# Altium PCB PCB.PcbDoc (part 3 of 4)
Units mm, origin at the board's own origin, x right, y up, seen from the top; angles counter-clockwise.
Board outline 114 x 86.5 mm, 4 copper layers (TOP, GND, SIG, BOTTOM), stack 1.586 mm thick; 98 components, 195 nets, 719 pads, 522 vias.
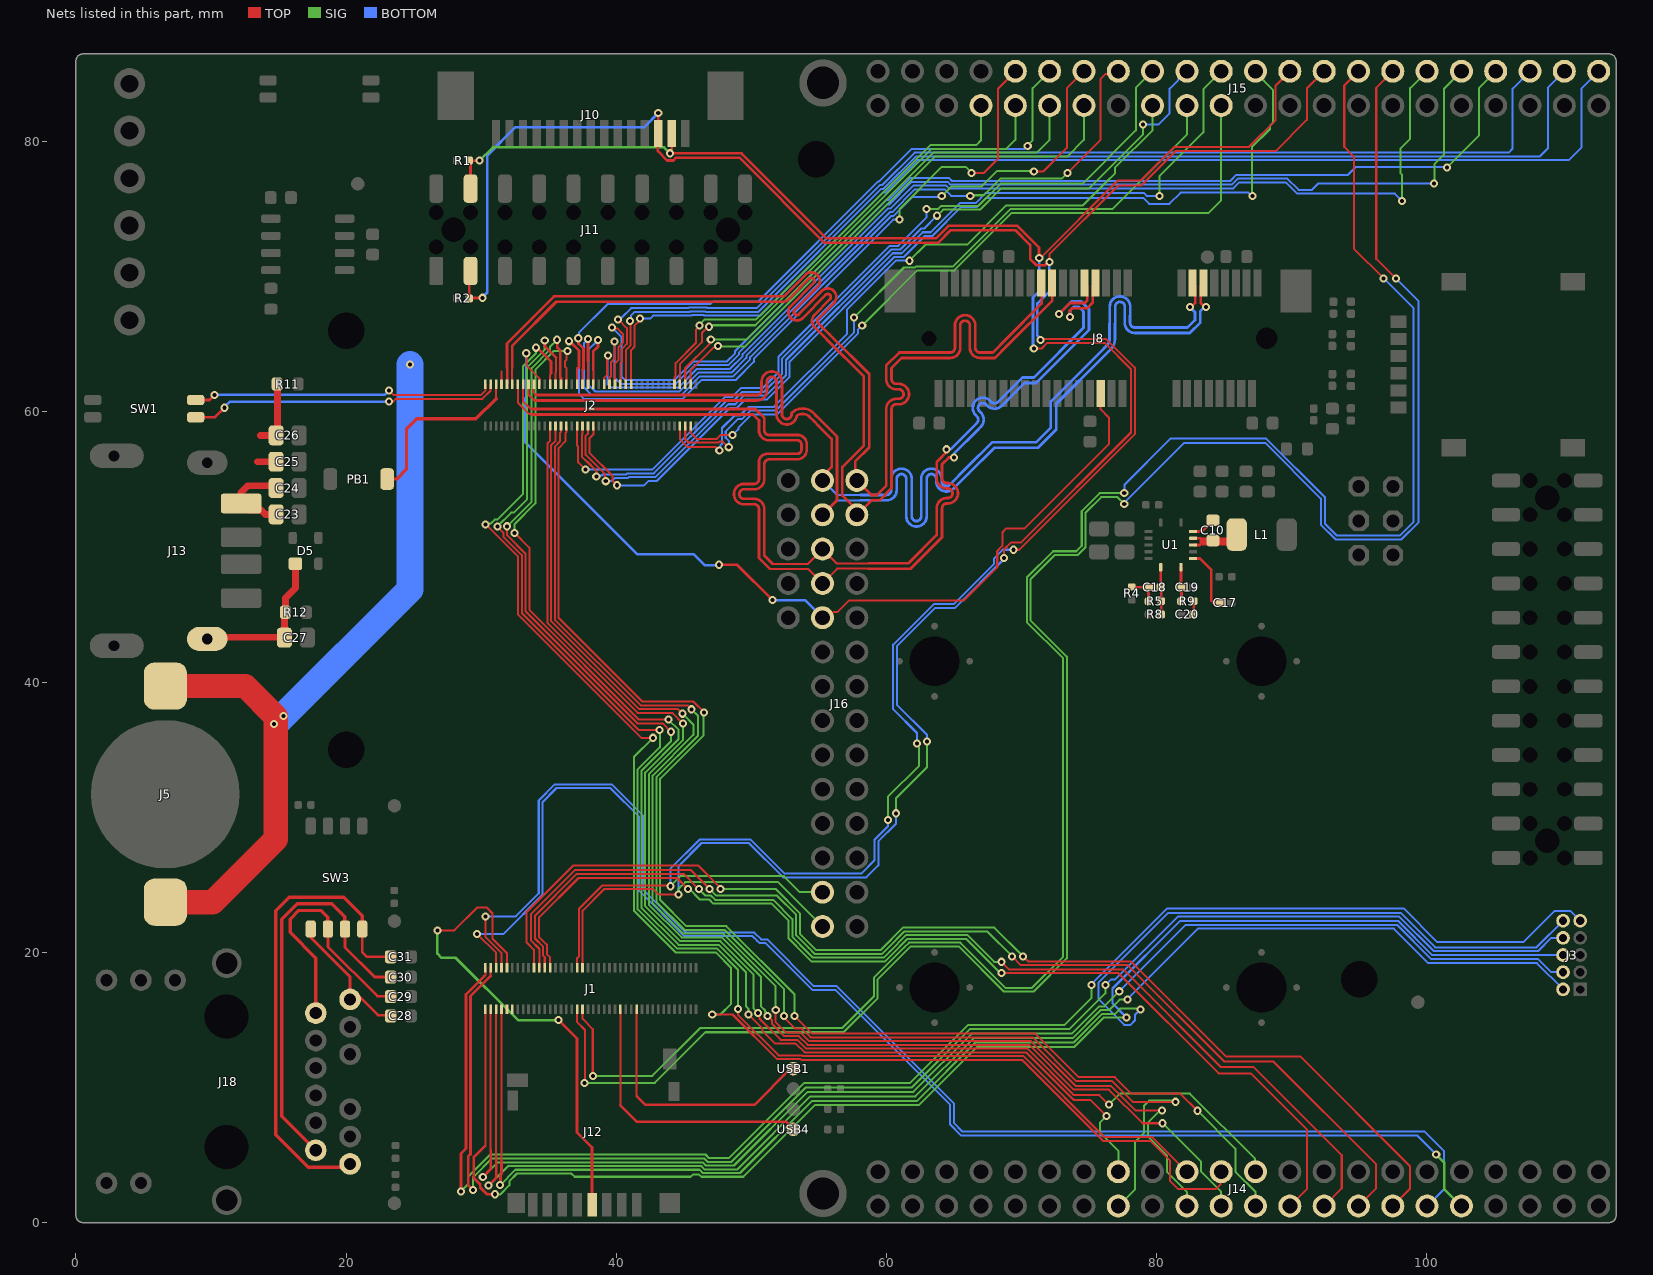
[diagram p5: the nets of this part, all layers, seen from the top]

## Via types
v1: diameter 0.6, hole 0.3, TOP to BOTTOM, tented both sides, 522 vias

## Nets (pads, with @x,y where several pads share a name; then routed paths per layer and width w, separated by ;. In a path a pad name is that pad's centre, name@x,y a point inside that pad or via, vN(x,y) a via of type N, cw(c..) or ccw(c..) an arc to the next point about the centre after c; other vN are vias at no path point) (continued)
I2C0.SCL_1: J1.46 J10.13 J11.3 J15.28 J16.25 R2.1 | length 197
  TOP w0.15: J1.46@37.1,18.86 37.1,19.567 37.222,19.689 37.222,23.207 38.974,24.959 43.932,24.959 v1(43.998,24.892) ; v1(69.39,49.801) 69.813,49.801 78.375,58.363 78.375,63.28 76.263,65.392 71.458,65.392 v1(71.388,65.322) ; v1(72.05,71.096) 72.05,71.669 77.145,76.764 78.856,76.764 81.393,79.301 88.803,79.301 91.12,81.617 91.12,83.946 J15.28@92.394,85.22
  TOP w0.2: J11.3@29.21,70.435 29.117,70.342 R2.1@29.117,68.411 29.137,68.431 30.067,68.431 v1(30.088,68.452) ; v1(43.103,82.118) 43.103,80.603 43.068,80.568 43.068,79.316 43.763,78.621 44.218,78.621 44.418,78.821 49.124,78.821 55.421,72.523 63.795,72.523 64.721,73.449 69.545,73.449 70.633,72.361 70.633,71.313 71.087,70.859 71.733,70.859 71.969,71.096 v1(72.05,71.096)
  SIG w0.15: v1(43.998,24.892) 44.741,25.635 52.397,25.635 53.582,24.449 J16.25@55.264,24.449 ; v1(60.098,29.792) 60.098,31.503 62.418,33.823 62.418,35.173 62.255,35.335 v1(62.255,35.457)
  BOTTOM w0.15: v1(43.998,24.892) 43.998,26.177 46.191,28.369 49.921,28.369 52.465,25.826 56.641,25.826 58.128,25.826 59.098,26.796 59.098,28.315 60.098,29.315 v1(60.098,29.792) ; v1(62.255,35.457) 62.255,36.233 60.494,37.995 60.494,42.768 63.498,45.772 64.965,45.772 67.966,48.772 67.966,49.17 68.597,49.801 v1(69.39,49.801)
  BOTTOM w0.2: v1(30.088,68.452) 30.088,68.489 30.442,68.843 30.442,78.99 32.538,81.086 42.071,81.086 v1(43.103,82.118) ; v1(71.388,65.322) 71.388,65.414 71.162,65.64 71.162,68.037 72.05,68.925 v1(72.05,71.096)
I2C0.SDA_1: J1.44 J10.14 J11.4 J15.26 J16.27 R1.1 | length 183.1
  TOP w0.15: J1.44@37.5,18.86 37.499,23.093 39.088,24.682 42.718,24.682 43.108,24.292 v1(44.598,24.292) ; v1(68.698,49.192) 68.698,49.819 69.209,50.33 69.95,50.33 78.098,58.478 78.098,63.165 76.155,65.109 71.884,65.109 71.475,64.7 v1(70.9,64.7) ; v1(71.305,71.386) 71.375,71.386 77.122,77.133 78.833,77.133 81.312,79.612 86.807,79.612 88.802,81.607 88.802,84.168 J15.26@89.854,85.22
  TOP w0.2: R1.1@29.1,78.6 29.112,78.612 R1.1@29.117,78.612 R1.1@29.128,78.601 ; J11.4@29.21,76.535 29.21,78.519 R1.1@29.128,78.601 ; v1(29.875,78.601) R1.1@29.128,78.601 ; J10.14@44.1,80.6 44.1,79.266 v1(43.982,79.148) 49.259,79.148 55.557,72.85 63.66,72.85 64.585,73.776 69.68,73.776 71.28,72.177 71.28,71.411 v1(71.305,71.386)
  SIG w0.15: v1(44.598,24.292) 44.598,24.702 45.09,25.194 51.979,25.194 J16.27@55.264,21.909 ; v1(60.698,30.292) 60.698,31.392 62.986,33.68 62.986,35.58 v1(62.998,35.592)
  SIG w0.2: v1(29.875,78.601) 30.864,79.59 43.539,79.59 v1(43.982,79.148)
  BOTTOM w0.15: v1(44.598,24.292) 44.598,26.385 46.305,28.092 49.807,28.092 52.35,25.549 58.512,25.549 59.401,26.438 59.401,28.226 60.698,29.524 v1(60.698,30.292) ; v1(62.998,35.592) 62.998,36.092 60.771,38.32 60.771,42.653 63.613,45.495 65.08,45.495 68.698,49.113 v1(68.698,49.192)
  BOTTOM w0.2: v1(70.9,64.7) 70.835,64.765 70.835,68.461 71.305,68.931 v1(71.305,71.386)
I2S.CK_1: J1.56 J14.25 | length 78.2
  TOP w0.15: J1.56@35.1,18.86 35.1,19.628 34.856,19.872 34.856,20.571 34.271,21.155 34.271,22.571 37.2,25.5 44.491,25.5 v1(45.298,24.692) ; v1(68.516,18.47) 77.158,18.47 84.583,11.045 86.955,11.045 91.13,6.87 91.13,2.496 J14.25@89.854,1.22
  SIG w0.15: v1(45.298,24.692) 45.388,24.692 46.167,23.913 46.877,23.913 47.188,23.602 51.498,23.602 52.755,22.345 52.755,21.756 52.755,21.024 53.998,19.781 54.441,19.338 59.9,19.338 60.342,19.781 61.553,20.991 65.883,20.991 68.404,18.47 v1(68.516,18.47)
I2S.SDI_1: J1.60 J14.29 | length 83.1
  TOP w0.15: J1.60@34.3,18.86 34.3,20.247 34.277,20.27 34.277,20.285 33.674,20.887 33.674,22.828 36.95,26.104 45.487,26.104 v1(46.898,24.692) ; v1(69.3,19.7) 69.951,19.049 77.857,19.049 84.986,11.92 88.638,11.92 96.219,4.339 96.219,2.505 J14.29@94.934,1.22
  SIG w0.15: v1(46.898,24.692) 47.4,24.19 51.894,24.19 53.309,22.775 53.309,21.985 53.309,21.254 54.227,20.335 54.67,19.892 59.67,19.892 60.113,20.335 61.323,21.545 67.455,21.545 v1(69.3,19.7)
I2S.SDO_1: J1.62 J14.31 | length 86.2
  TOP w0.15: J1.62@33.9,18.86 33.9,20.199 33.347,20.752 33.347,22.964 36.814,26.431 46.059,26.431 47.698,24.792 v1(47.698,24.692) ; v1(70.1,19.7) 70.474,19.326 78.088,19.326 85.119,12.296 90.622,12.296 98.75,4.168 98.75,2.496 J14.31@97.474,1.22
  SIG w0.15: v1(47.698,24.692) 51.783,24.692 53.586,22.89 53.586,21.368 54.785,20.169 59.555,20.169 61.208,21.822 67.978,21.822 v1(70.1,19.7)
I2S.WS_1: J1.58 J14.27 | length 80.2
  TOP w0.15: J1.58@34.7,18.86 34.7,19.636 34.579,19.758 34.579,20.421 33.976,21.023 33.976,22.703 37.075,25.802 44.988,25.802 v1(46.108,24.682) ; v1(68.5,19.3) 69.053,18.747 77.517,18.747 84.756,11.508 87.178,11.508 93.696,4.99 93.696,2.522 J14.27@92.394,1.22
  SIG w0.15: v1(46.108,24.682) 46.6,24.19 47.009,24.19 47.32,23.879 51.613,23.879 53.032,22.46 53.032,21.871 53.032,21.139 54.113,20.058 54.556,19.615 59.785,19.615 60.228,20.058 61.438,21.268 65.998,21.268 67.966,19.3 v1(68.5,19.3)
JTAG.R\E\S\E\T\_1: J1.73 J3.10 | length 110.3
  TOP w0.15: 31.5,4.538 J1.73@31.5,15.78
  TOP w0.2: v1(31.395,2.772) 31.427,2.805 31.427,3.517 31.5,3.59 31.5,4.538
  SIG w0.15: v1(31.395,2.772) 32.529,3.907 46.161,3.907 46.402,3.665 49.156,3.665 54.503,9.013 62.263,9.013 66.577,13.327 73.851,13.327 75.976,15.452 76.922,15.452 77.301,15.832 78.746,15.832 v1(78.804,15.774)
  BOTTOM w0.15: v1(78.804,15.774) 78.395,15.365 78.395,14.959 78.073,14.636 77.595,14.636 75.695,16.536 75.695,17.783 80.839,22.927 98.065,22.927 100.617,20.374 108.113,20.374 J3.10@110.079,22.34
JTAG.TCK/SCK_1: J1.77 J3.4 | length 102
  TOP w0.15: 30.7,5.349 J1.77@30.7,15.78
  TOP w0.2: v1(30.114,3.358) 30.7,3.944 30.7,5.349
  SIG w0.15: v1(30.114,3.358) 31.217,4.461 46.39,4.461 46.632,4.219 48.707,4.219 54.155,9.667 61.992,9.667 66.306,13.981 73.722,13.981 75.747,16.006 76.117,16.006 v1(77.227,17.116)
  BOTTOM w0.15: v1(77.227,17.116) 82.142,22.031 97.785,22.031 100.293,19.523 108.208,19.523 109.201,18.53 J3.4@110.079,18.53
JTAG.TDI_1: J1.78 J3.8 | length 108.9
  TOP w0.15: 30.7,18.256 J1.78@30.7,18.86
  TOP w0.2: v1(29.4,2.4) 29.036,2.764 29.036,4.892 29.198,5.055 29.198,16.754 30.7,18.256
  SIG w0.15: v1(29.4,2.4) 29.4,3.353 30.784,4.738 46.505,4.738 46.747,4.496 48.522,4.496 54.019,9.994 61.857,9.994 66.17,14.308 73.536,14.308 76.197,16.969 v1(76.197,17.575)
  BOTTOM w0.15: v1(76.197,17.575) 76.601,17.979 76.895,17.979 81.566,22.65 97.95,22.65 100.503,20.097 108.228,20.097 109.201,21.07 J3.8@110.079,21.07
JTAG.TDO/SWO_1: J1.79 J3.6 | length 106.8
  TOP w0.15: 30.3,5.694 J1.79@30.3,15.78
  TOP w0.2: 30.3,5.694 29.45,4.844 29.45,3.276 29.927,2.799 29.927,2.594 30.429,2.092 v1(31.019,2.092)
  SIG w0.15: v1(31.019,2.092) 31.424,2.092 32.087,2.754 32.087,3.071 32.646,3.63 36.671,3.63 36.913,3.388 45.504,3.388 45.688,3.572 46.104,3.572 46.288,3.388 49.402,3.388 54.7,8.686 62.398,8.686 66.712,13 73.916,13 76.091,15.175 v1(77.766,15.175)
  BOTTOM w0.15: v1(77.766,15.175) 76.725,16.216 76.725,17.324 81.709,22.308 97.9,22.308 100.408,19.8 J3.6@110.079,19.8
JTAG.TMS/SWD_1: J1.75 J3.2 | length 102.8
  TOP w0.15: 31.1,4.883 J1.75@31.1,15.78
  TOP w0.2: v1(30.534,2.732) 31.1,3.298 31.1,4.883
  SIG w0.15: v1(30.534,2.732) 31.986,4.184 46.276,4.184 46.517,3.942 48.97,3.942 54.368,9.34 62.128,9.34 66.441,13.654 73.786,13.654 75.861,15.729 76.489,15.729 77.26,16.5 v1(77.85,16.5)
  BOTTOM w0.15: v1(77.85,16.5) 77.85,16.566 83.039,21.754 97.557,21.754 100.111,19.2 108.139,19.2 J3.2@110.079,17.26
JTAG.TRST_1: J1.80 J3.9 | length 112.3
  TOP w0.15: 30.206,18.224 30.3,18.319 J1.80@30.3,18.86
  TOP w0.2: v1(28.5,2.3) 28.5,5.107 28.871,5.478 28.871,16.89 30.206,18.224
  SIG w0.15: v1(28.5,2.3) 29.02,2.82 29.02,3.389 30.666,5.035 46.599,5.035 46.861,4.773 48.336,4.773 53.884,10.321 61.721,10.321 66.035,14.635 73.18,14.635 75.161,16.616 v1(75.161,17.59)
  BOTTOM w0.15: v1(75.161,17.59) 75.161,17.64 80.771,23.25 98.282,23.25 100.773,20.758 107.138,20.758 109.43,23.05 110.639,23.05 J3.9@111.349,22.34
LICELL_1: J2.7 J5.1 J5.2 | length 59.7
  TOP w0.15: J2.7@31.5,62.04 31.5,62.978
  TOP w1.8: J5.1@6.618,23.712 10.134,23.712 14.794,28.372 14.794,37.445 12.527,39.712 J5.2@6.618,39.712
  BOTTOM w2: 14.927,37.064 v1(15.369,37.506) 24.723,46.86 v1(24.723,63.509)
  other v1: 14.669,36.906
mPCIe_CK_N: J2.19 J8.11 J16.3 | length 86.5
  TOP w0.15: J2.19@33.9,62.04 33.884,62.024 33.884,61.435 34.049,61.269
  TOP w0.2: 34.049,61.269 34.067,61.252 50.096,61.252 50.396,61.252 ccw(c50.396,61.606) 50.75,61.606 50.75,62.246 cw(c51.504,62.246) 52.258,62.246 52.258,59.825 ccw(c52.612,59.825) 52.966,59.825 cw(c53.166,59.825) 53.036,59.977 cw(c53.784,59.109) 54.593,59.92 54.798,59.716 55,59.514 56.341,58.172 56.341,53.466 55.612,52.737 55.264,52.737 J16.3@55.264,52.389 ; J8.11@83.456,69.55 83.26,69.354 83.26,68.053 83.552,67.761 v1(83.651,67.761)
  BOTTOM w0.15: J16.3@55.264,52.389 56.334,53.459 58.08,53.459
  BOTTOM w0.2: 58.08,53.459 59.7,53.459 60,53.459 ccw(c60,54.213) 60.754,54.213 60.754,55.052 cw(c61.108,55.052) 61.462,55.052 61.462,52.277 ccw(c62.216,52.277) 62.97,52.277 62.97,55.052 cw(c63.324,55.052) 63.678,55.052 63.678,54.866 ccw(c64.432,54.866) 64.965,54.333 66.076,55.444 67.982,57.349 71.223,57.349 72.564,58.691 72.564,60.607 76.121,64.164 76.574,64.617 ccw(c75.763,65.426) 76.909,65.416 76.929,67.803 cw(c77.283,67.799) 77.286,68.153 ccw(c77.288,68.353) 77.287,68.153 cw(c77.283,67.799) 77.637,67.795 77.627,66.611 ; 77.627,66.61 ccw(c78.381,66.603) 78.381,65.849 80.064,65.849 82.446,65.849 83.23,66.633 83.23,67.459 v1@83.391,67.621
mPCIe_CK_P: J2.17 J8.13 J16.1 | length 83.1
  TOP w0.15: J2.17@33.5,62.04 33.5,61.288 33.937,60.852
  TOP w0.2: 33.937,60.852 50.096,60.852 50.396,60.852 ccw(c50.396,61.606) 51.15,61.606 51.15,62.246 cw(c51.504,62.246) 51.858,62.246 51.858,59.825 ccw(c52.612,59.825) 53.359,59.722 cw(c53.784,59.109) 54.31,59.637 54.617,59.331 54.976,58.971 55.941,58.007 55.941,55.914 55.264,55.237 J16.1@55.264,54.929 ; v1(82.451,67.761) 82.55,67.761 82.842,68.053 82.842,69.364 J8.13@82.656,69.55
  BOTTOM w0.15: J16.1@55.264,54.929 56.334,53.859 58.08,53.859
  BOTTOM w0.2: 58.08,53.859 59.7,53.859 60,53.859 ccw(c60,54.213) 60.354,54.213 60.354,55.052 cw(c61.108,55.052) 61.862,55.052 61.862,52.277 ccw(c62.216,52.277) 62.57,52.277 62.57,55.052 cw(c63.324,55.052) 64.078,55.052 64.078,54.866 ccw(c64.432,54.866) 64.682,54.616 65.973,55.906 67.816,57.749 71.057,57.749 72.164,58.856 72.164,60.773 76.126,64.734 76.291,64.899 ccw(c75.763,65.426) 76.509,65.42 76.529,67.805 cw(c77.283,67.799) 77.29,68.553 cw(c77.283,67.799) 78.033,67.882 78.037,67.877 78.037,67.805 cw(c77.283,67.799) 78.037,67.794 78.027,66.605 ccw(c78.381,66.603) 78.381,66.249 80.067,66.249 82.28,66.249 82.83,66.799 82.83,67.382 v1(82.451,67.761)
mPCIe_RST: J2.21 J8.22 J16.9 | length 68.6
  TOP w0.15: v1(33.333,64.347) 33.333,63.457 34.3,62.49 J2.21@34.3,62.04 ; J16.9@55.264,44.769 55.67,44.769 56.1,45.2 56.376,45.2 57.226,46.049 65.736,46.049 68.196,48.51 68.196,49.709 68.576,50.089 68.576,51.08 68.877,51.381 70.218,51.381 76.462,57.625 76.462,59.588 75.856,60.194 J8.22@75.856,61.35
  TOP w0.2: v1(47.598,48.692) 48.947,48.692 v1(51.567,46.071)
  BOTTOM w0.2: v1(33.333,64.347) 33.333,61.063 33.23,60.96 33.23,57.783 41.555,49.459 45.739,49.459 46.548,48.649 47.556,48.649 v1(47.598,48.692) ; v1(51.567,46.071) 53.962,46.071 J16.9@55.264,44.769
mPCIe_RX_N: J2.15 J8.23 J16.5 | length 83.1
  TOP w0.15: J2.15@33.1,62.04 33.075,62.015 33.075,61.715 33.075,60.806 33.646,60.236 33.681,60.236 ; 51.574,48.762 51.599,48.737 54.152,48.737 J16.5@55.264,49.849 56.328,48.786 58.7,48.786
  TOP w0.2: 33.681,60.236 33.699,60.218 50.282,60.218 50.955,59.545 50.955,58.645 ccw(c51.3,58.645) 51.3,58.3 53.4,58.3 cw(c53.4,57.6) 54.1,57.6 54.1,57.218 cw(c53.382,57.218) 53.382,56.5 51.34,56.5 ccw(c51.34,56.115) 50.955,56.115 50.955,56.105 50.955,55.028 cw(c50.201,55.028) 50.201,54.274 49.454,54.274 ccw(c49.454,53.92) 49.454,53.566 50.201,53.566 cw(c50.201,52.812) 50.955,52.812 50.955,52.512 50.955,49.357 51.549,48.762 51.574,48.762 ; 58.7,48.8 61.619,48.8 63.71,50.891 63.71,51.964 63.71,52.873 cw(c64.464,52.873) 64.464,53.627 64.532,53.627 ccw(c64.532,53.981) 64.532,54.335 64.464,54.335 cw(c64.464,55.089) 63.71,55.089 63.71,55.389 63.71,56.295 63.827,56.412 64.45,57.035 v1(64.45,57.237) ; v1(73.585,67.022) 73.562,67.045 73.562,67.494 73.736,67.667 74.839,67.667 75.256,68.084 75.256,69.35 J8.23@75.456,69.55
  BOTTOM w0.2: v1(64.45,57.237) 64.747,57.237 66.475,58.966 66.687,59.178 ccw(c66.437,59.428) 66.687,59.679 66.596,59.77 cw(c67.129,60.303) 66.596,60.836 cw(c67.129,60.303) 67.662,60.836 67.738,60.761 67.754,60.744 ccw(c68.004,60.995) 68.254,60.745 69.277,61.768 70.06,62.55 70.901,62.55 74.585,66.234 74.585,67.436 74.248,67.773 73.853,67.773 73.575,67.495 73.575,67.032 v1(73.585,67.022)
mPCIe_RX_P: J2.13 J8.25 J16.7 | length 85.6
  TOP w0.15: J2.13@32.7,62.04 32.725,62.015 32.725,60.661 33.543,59.843 33.75,59.843 33.775,59.818 ; 51.361,48.385 51.498,48.385 51.5,48.387 54.186,48.387 J16.7@55.264,47.309 56.351,48.397 58.666,48.397 58.667,48.395
  TOP w0.2: 33.775,59.818 50.116,59.818 50.555,59.379 50.555,58.645 ccw(c51.3,58.645) 51.3,57.9 53.4,57.9 cw(c53.4,57.6) 53.7,57.6 53.7,57.218 cw(c53.382,57.218) 53.382,56.9 51.174,56.9 ccw(c51.174,56.281) 50.555,56.281 50.555,56.105 50.555,55.028 cw(c50.201,55.028) 50.201,54.674 49.454,54.674 ccw(c49.454,53.92) 49.454,53.166 50.201,53.166 cw(c50.201,52.812) 50.555,52.812 50.555,52.512 50.555,49.191 51.361,48.385 ; 58.667,48.395 61.78,48.395 64.11,50.725 64.11,51.964 64.11,52.873 cw(c64.464,52.873) 64.464,53.227 64.532,53.227 ccw(c64.532,53.981) 64.532,54.735 64.464,54.735 cw(c64.464,55.089) 64.11,55.089 64.11,55.389 64.11,56.13 64.611,56.631 v1(65,56.631) ; v1@72.764,67.261 73.57,68.067 74.673,68.067 74.856,68.25 74.856,69.35 J8.25@74.656,69.55
  BOTTOM w0.2: v1(65,56.631) 65.003,56.631 65.003,56.928 66.758,58.683 66.97,58.895 ccw(c66.437,59.428) 67.029,59.896 67.029,59.903 66.879,60.053 cw(c67.129,60.303) 66.879,60.553 cw(c67.129,60.303) 67.38,60.553 67.47,60.463 ccw(c68.004,60.995) 68.537,60.462 69.56,61.485 70.225,62.15 71.066,62.15 74.985,66.069 74.985,67.602 74.414,68.173 73.688,68.173 v1(72.764,67.249)
mPCIe_TX_N: J2.11 J8.31 J16.4 | length 88.1
  TOP w0.15: J2.11@32.3,62.04 32.275,62.065 32.275,62.365 32.275,63.249 32.3,63.274
  TOP w0.2: 32.3,63.274 32.3,64.905 35.554,68.159 46.606,68.159 ; 46.606,68.158 51.556,68.158 52.328,68.158 ccw(c52.328,68.785) 52.775,68.346 54.271,69.867 cw(c54.433,69.709) 54.593,69.87 cw(c54.433,69.709) 54.596,69.55 52.858,67.783 52.858,67.774 ccw(c53.362,67.402) 52.863,67.023 52.863,67.014 52.916,66.961 ccw(c53.362,67.402) 52.922,66.956 52.98,66.897 52.99,66.897 ccw(c53.362,67.402) 53.809,66.962 ccw(c53.667,67.102) 53.81,66.963 55.489,68.67 ; 54.66,66.292 cw(c55.103,66.736) 54.656,67.176 55.813,68.353 ccw(c55.651,68.511) 55.811,68.673 cw(c55.95,68.816) 55.81,68.674 ccw(c55.651,68.511) 55.489,68.67 ; 54.661,66.292 55.494,65.459 55.649,65.304 58.319,62.633 58.319,57.531 56.727,55.938 56.727,53.814 57.804,52.737 J16.4@57.804,52.389 58.874,53.459 59.465,53.459 60.372,54.366 60.372,58.996 60.372,60.216 cw(c60.726,60.216) 60.726,60.57 60.906,60.57 ccw(c60.906,61.324) 60.906,62.078 60.726,62.078 cw(c60.726,62.432) 60.372,62.432 60.372,62.732 60.372,63.257 61.114,64 64.408,64 64.708,64 ccw(c64.708,64.754) 65.462,64.754 65.462,66.406 cw(c65.816,66.406) 66.17,66.406 66.17,64.754 ccw(c66.924,64.754) 66.924,64 68.032,64 68.9,64.868 72.273,68.24 J8.31@72.273,69.667
mPCIe_TX_P: J2.9 J8.33 J16.2 | length 85.4
  TOP w0.15: J2.9@31.9,62.04 31.925,62.065 31.925,62.365 31.925,63.249 31.9,63.274
  TOP w0.2: 31.9,63.274 31.9,65.071 35.388,68.559 46.772,68.559 51.684,68.558 52.328,68.558 ccw(c52.328,68.785) 52.489,68.626 53.987,70.149 ; 53.987,70.149 cw(c54.433,69.709) 53.993,70.155 54.046,70.208 54.054,70.208 cw(c54.433,69.709) 54.873,70.156 ; 54.873,70.156 cw(c54.433,69.709) 54.88,70.149 54.932,70.096 54.932,70.088 cw(c54.433,69.709) 54.88,69.269 ; 54.88,69.268 53.201,67.561 ccw(c53.362,67.402) 53.203,67.24 ccw(c53.362,67.402) 53.523,67.242 55.204,68.951 ; 55.205,68.952 cw(c55.651,68.511) 55.211,68.957 55.264,69.011 55.272,69.011 cw(c55.651,68.511) 56.091,68.958 cw(c55.651,68.511) 56.098,68.072 ; 56.098,68.071 54.941,66.895 ccw(c55.103,66.736) 54.942,66.576 55.777,65.742 55.929,65.589 58.719,62.799 58.719,57.365 57.679,56.324 57.679,55.055 J16.2@57.804,54.929 58.874,53.859 59.299,53.859 59.972,54.532 59.972,58.996 59.972,60.216 cw(c60.726,60.216) 60.726,60.97 60.906,60.97 ccw(c60.906,61.324) 60.906,61.678 60.726,61.678 cw(c60.726,62.432) 59.972,62.432 59.972,62.732 59.972,63.423 60.949,64.4 64.408,64.4 64.708,64.4 ccw(c64.708,64.754) 65.062,64.754 65.062,66.406 cw(c65.816,66.406) 66.57,66.406 66.57,64.754 ccw(c66.924,64.754) 66.924,64.4 67.867,64.4 68.9,65.433 71.481,68.014 J8.33@71.481,69.626
NetC10_1: C10.1 U1.13 | length 1.8
  TOP w0.2: U1.13@82.699,51.159 83.338,51.159 C10.1@84.163,51.984
NetC10_2: C10.2 L1.1 U1.11 U1.12 | length 4.4
  TOP w0.2: U1.11@82.699,50.159 83.194,50.159 83.459,50.424 83.224,50.659 U1.12@82.699,50.659
  TOP w0.6: 83.459,50.424 85.423,50.424 L1.1@85.925,50.926
NetC17_1: C17.1 U1.9 | length 4.6
  TOP w0.2: U1.9@82.699,49.159 83.197,49.159 84.032,48.324 84.032,46.054 84.19,45.895 C17.1@84.655,45.895
NetC18_1: C18.1 R5.1 R8.2 U1.7 | length 3.5
  TOP w0.2: U1.7@80.299,48.509 C18.1@80.299,47.025 80.339,46.985 R5.1@80.339,45.994 R8.2@80.339,45.013
NetC18_2: C18.2 R4.1 R5.2 | length 2.3
  TOP w0.2: R4.1@78.155,47.046 78.176,47.025 C18.2@79.429,47.025 79.389,46.985 R5.2@79.389,45.994
NetC19_2: C19.2 R9.2 U1.8 | length 2.5
  TOP w0.2: R9.2@81.794,45.994 81.834,46.034 C19.2@81.834,47.025 81.799,47.06 U1.8@81.799,48.509
NetC20_2: C20.2 R9.1 | length 1
  TOP w0.2: C20.2@82.704,45.013 82.744,45.053 R9.1@82.744,45.994
NetC23_2: C23.2 C24.2 C25.2 C26.2 J13.1 R11.2 | length 12.8
  TOP w0.5: 13.414,56.318 C25.2@14.814,56.318 ; 13.636,58.256 C26.2@14.802,58.256 ; C23.2@14.814,52.418 14.022,52.418 13.693,52.748 12.697,52.748 J13.1@12.222,53.223 12.222,54.048 12.719,54.545 14.638,54.545 C24.2@14.814,54.368 ; C26.2@14.814,58.268 14.911,58.365 R11.2@14.911,61.847 ; R11.2@14.889,62.068 R11.2@14.911,62.047
NetC27_2: C27.2 D5.1 J13.SHIELD2 R12.2 | length 11.3
  TOP w0.5: J13.SHIELD2@9.722,43.323 15.407,43.323 C27.2@15.43,43.3 15.43,44.975 R12.2@15.455,45 ; R12.2@15.505,45.173 15.505,46.237 16.243,46.975 D5.1@16.243,48.767
NetC28_1: C28.1 J18.12 SW3.1 | length 10
  TOP w0.2: SW3.1@17.379,21.726 17.379,21.105 20.292,18.193 J18.12@20.292,16.515 ; J18.12@20.528,17.172 22.351,15.349 23.234,15.349 C28.1@23.295,15.288
NetC29_1: C29.1 J18.6 SW3.2 | length 19.4
  TOP w0.2: SW3.2@18.649,21.726 18.649,20.41 22.307,16.752 23.27,16.752 C29.1@23.3,16.723
  TOP w0.25: J18.6@17.752,15.5 17.752,19.577 15.855,21.473 15.855,22.455 16.5,23.1 18.136,23.1 18.649,22.587 SW3.2@18.649,21.726
NetC30_1: C30.1 J18.1 SW3.3 | length 30.2
  TOP w0.2: SW3.3@19.919,21.726 19.919,20.37 22.119,18.17 C30.1@23.292,18.17
  TOP w0.25: J18.1@17.752,5.35 15.24,7.862 15.24,22.455 16.385,23.6 18.945,23.6 19.9,22.645 19.9,21.745 SW3.3@19.919,21.726
NetC31_1: C31.1 J18.7 SW3.4 | length 35.2
  TOP w0.2: SW3.4@21.189,21.726 21.189,20.014 21.534,19.669 C31.1@23,19.669
  TOP w0.25: J18.7@20.292,4.335 20.057,4.1 17.202,4.1 14.8,6.502 14.8,23.081 15.79,24.07 19.83,24.07 21.189,22.711 SW3.4@21.189,21.726
NetJ1_23: J1.23 USB1.X | length 19.5
  TOP w0.15: 41.5,9.359 J1.23@41.5,15.78
  TOP w0.2: 41.5,9.359 42.149,8.71 50.224,8.71 52.906,11.392 USB1.X@53.098,11.392 ; USB1.X@53.061,10.984 USB1.X@53.098,11.021
NetJ1_29: J1.29 USB4.X | length 20.6
  TOP w0.15: 40.3,8.679 J1.29@40.3,15.78
  TOP w0.2: 40.3,8.679 41.522,7.457 52.586,7.457 USB4.X@53.098,6.945
NetJ1_43: J1.43 J15.30 | length 151.7
  TOP w0.15: J1.43@37.5,15.78 37.5,15.07 38.253,14.316 38.253,10.873 v1(38.268,10.858) ; J15.30@94.934,85.22 93.882,84.168 93.882,79.621 94.6,78.903 94.6,72.091 v1(96.798,69.892)
  SIG w0.15: v1(38.268,10.858) 42.663,10.858 46.205,14.4 56.736,14.4 59.067,16.731 59.067,18.113 61.327,20.373 61.667,20.714 65.459,20.714 65.8,20.373 68.796,17.378 70.771,17.378 73.067,19.674 73.067,41.77 70.394,44.443 70.394,47.748 72.336,49.69 74.045,49.69 74.451,50.096 74.451,52.661 75.782,53.992 v1(77.598,53.992)
  BOTTOM w0.15: v1(77.598,53.992) 77.598,54.592 81.048,58.042 88.087,58.042 92.457,53.672 92.457,51.73 93.347,50.84 98.002,50.84 99.025,51.863 99.025,67.666 v1(96.798,69.892)
NetJ1_45: J1.45 J15.32 | length 152.6
  TOP w0.15: J1.45@37.1,15.78 37.1,14.826 37.678,14.249 37.678,10.371 v1(37.65,10.343) ; J15.32@97.474,85.22 96.25,83.996 96.25,71.341 v1(97.698,69.892)
  SIG w0.15: v1(37.65,10.343) 42.843,10.343 46.585,14.085 56.812,14.085 59.344,16.616 59.344,17.999 61.782,20.437 65.345,20.437 68.681,17.101 70.886,17.101 73.344,19.559 73.344,41.884 70.671,44.558 70.671,47.633 72.45,49.413 74.16,49.413 74.728,49.981 74.728,50.62 74.728,52.546 75.88,53.699 76.153,53.699 76.157,53.694 77.096,53.694 v1(77.598,53.192)
  BOTTOM w0.15: v1(77.598,53.192) 77.598,53.282 82.024,57.708 88.029,57.708 92.155,53.582 92.155,51.64 93.232,50.563 98.117,50.563 99.382,51.828 99.382,68.209 v1(97.698,69.892)
NetJ1_69: J1.69
NetJ1_71: J1.71
NetJ1_72: J1.72 J12.4 | length 36.9
  TOP w0.15: v1(26.762,21.628) 28.016,21.628 29.704,23.316 30.395,23.316 30.833,22.878 30.833,21.019 31.9,19.953 J1.72@31.9,18.86
  TOP w0.2: v1(35.721,14.979) 37.088,13.612 37.088,6.677 38.2,5.566 J12.4@38.2,1.312
  SIG w0.2: v1(26.762,21.628) 26.746,21.611 26.746,19.905 27.055,19.596 28.112,19.596 32.729,14.979 v1(35.721,14.979)
NetJ1_74: J1.74 J14.33 | length 103.2
  TOP w0.15: v1(30.301,22.664) 30.301,21.16 31.496,19.965 J1.74@31.496,18.864
  BOTTOM w0.15: v1(30.301,22.664) 30.305,22.668 32.563,22.668 34.256,24.362 34.256,31.24 35.456,32.439 38.336,32.439 39.667,32.439 41.96,30.146 41.96,24.664 45.154,21.471 50.196,21.471 50.205,21.461 50.219,21.461 50.722,20.959 51.17,20.959 54.628,17.501 56.307,17.501 64.984,8.824 64.984,7.377 65.626,6.735 99.83,6.735 101.274,5.29 101.274,2.48 J14.33@100.014,1.22
NetJ1_76: J1.76 J14.35 | length 102.4
  TOP w0.15: v1(29.7,21.35) 29.719,21.35 31.1,19.969 J1.76@31.1,18.879
  SIG w0.2: v1(100.689,5.033) 101.279,4.444 101.279,2.495 J14.35@102.554,1.22
  BOTTOM w0.15: v1(29.7,21.35) 29.706,21.344 31.63,21.344 34.533,24.247 34.533,31.125 35.57,32.162 39.553,32.162 41.683,30.031 41.683,24.549 45.039,21.194 50.081,21.194 50.419,20.855 50.434,20.855 50.607,20.682 51.055,20.682 54.514,17.224 56.192,17.224 64.707,8.709 64.707,7.256 65.505,6.458 99.265,6.458 v1(100.689,5.033)
NetJ2_1: J2.1 SW1.2 | length 22.5
  TOP w0.15: v1(23.173,61.591) 23.518,61.245 29.964,61.245 30.3,61.582 J2.1@30.3,62.04
  TOP w0.2: SW1.2@8.921,60.826 SW1.2@8.865,60.882 9.877,60.882 v1(10.264,61.268)
  BOTTOM w0.2: v1(10.264,61.268) 22.851,61.268 v1(23.173,61.591)
NetJ2_3: J2.3 SW1.1 | length 23.1
  TOP w0.15: v1(23.164,60.766) 23.472,60.766 23.674,60.968 30.078,60.968 30.7,61.59 J2.3@30.7,62.04
  TOP w0.2: SW1.1@8.865,59.612 10.302,59.612 v1(11,60.31)
  BOTTOM w0.2: v1(11,60.31) 11,60.379 11.388,60.766 v1(23.164,60.766)
NetJ2_5: J2.5 PB1.2 | length 13.4
  TOP w0.15: 31.1,60.985 J2.5@31.1,62.04
  TOP w0.25: PB1.2@22.979,55.035 23.747,55.035 24.465,55.753 24.465,58.718 25.232,59.485 29.6,59.485 31.1,60.985
NetJ2_25: J2.25 J14.22 | length 111.3
  TOP w0.15: v1(30.325,51.679) 32.724,49.28 32.724,45.004 41.846,35.882 v1(42.722,35.882) ; J2.25@35.1,62.04 35.1,62.696 35.159,62.875 ; v1(47.1,15.4) 48.598,15.4 51.904,12.094 53.646,12.094 53.702,12.038 70.028,12.038 76.021,6.045 79.508,6.045 80.992,4.562 80.992,3.07 81.572,2.49 84.393,2.49 84.713,2.81 84.713,3.699 J14.22@84.774,3.76
  TOP w0.2: v1(34.058,64.756) 34.128,64.756 35.159,63.725 35.159,62.875
  SIG w0.15: v1(30.325,51.679) 30.388,51.742 30.704,51.742 30.985,52.023 31.175,52.023 33.1,53.948 33.1,63.405 34.052,64.356 34.052,64.75 v1(34.058,64.756) ; v1(42.722,35.882) 41.304,34.465 41.304,23.069 44.379,19.994 47.347,19.994 48.502,18.838 48.502,16.192 47.71,15.4 v1(47.1,15.4)
NetJ2_26: J2.26 J14.21 | length 96.4
  TOP w0.15: J2.26@35.1,58.96 35.1,57.875 34.893,57.668 34.893,44.402 41.57,37.725 44.133,37.725 v1(44.92,36.937) ; v1(51.2,15.3) 51.521,14.979 51.521,14.715 52.439,13.798 53.509,13.798 54.161,13.146 70.572,13.146 73.874,9.844 76.465,9.844 78.96,7.349 v1(80.434,7.349)
  SIG w0.15: v1(44.92,36.937) 44.92,35.701 42.412,33.194 42.412,23.528 44.838,21.102 47.806,21.102 50.696,18.211 50.696,16.014 51.002,15.708 51.002,15.62 51.2,15.422 v1(51.2,15.3) ; v1(80.434,7.349) 83.286,4.497 83.286,3.76 84.774,2.272 J14.21@84.774,1.22
NetJ2_27: J2.27 J14.20 | length 104.5
  TOP w0.15: v1(31.193,51.521) 31.643,51.071 31.643,50.753 33.001,49.395 33.001,45.119 41.676,36.444 v1(43.183,36.444) ; J2.27@35.5,62.04 35.5,62.93 35.529,62.959 35.529,64.033 ; v1(49,15.8) 49,15.39 52.019,12.371 53.76,12.371 53.817,12.315 70.143,12.315 76.136,6.322 79.672,6.322 J14.20@82.234,3.76
  TOP w0.2: v1(34.7,65.3) 34.718,65.282 34.718,64.844 35.529,64.033
  SIG w0.15: v1(31.193,51.521) 32.215,52.543 32.414,52.543 33.402,53.531 33.402,63.315 34.7,64.613 v1(34.7,65.3) ; v1(43.183,36.444) 43.224,36.403 43.224,35.18 41.581,33.538 41.581,23.183 44.494,20.271 47.461,20.271 49,18.732 v1(49,15.8)
NetJ2_28: J2.28 J14.19 | length 97.1
  TOP w0.15: J2.28@35.5,58.96 35.5,57.884 35.17,57.554 35.17,44.517 41.685,38.002 44.566,38.002 v1(44.903,37.664) ; v1(51.798,15.72) 51.798,14.83 52.553,14.075 53.624,14.075 54.276,13.423 70.687,13.423 73.988,10.122 76.591,10.122 78.414,8.299 v1(80.379,8.299)
  SIG w0.15: v1(44.903,37.664) 45.703,36.865 45.703,36.092 42.689,33.079 42.689,23.642 44.953,21.379 47.92,21.379 51.798,17.501 v1(51.798,15.72) ; v1(80.379,8.299) 80.266,8.299 79.339,7.373 79.339,6.376 80.746,4.97 80.746,3.76 82.234,2.272 J14.19@82.234,1.22
NetJ2_29: J2.29 J14.16 | length 101.5
  TOP w0.15: v1(31.92,51.538) 31.92,50.868 33.278,49.51 33.278,45.234 41.566,36.946 43.425,36.946 v1(44.041,36.33) ; J2.29@35.9,62.04 35.9,62.49 ; v1(49.776,15.41) 50.81,14.377 50.81,14.192 51.758,13.244 53.279,13.244 53.932,12.592 70.322,12.592 73.838,9.075 75.075,9.075 76.262,7.888 v1(76.296,7.888)
  TOP w0.2: v1(35.614,65.347) 35.627,65.334 35.627,64.769 35.858,64.537 35.858,62.532 35.9,62.49
  SIG w0.15: v1(31.92,51.538) 33.729,53.347 33.729,63.25 35.078,64.599 35.078,64.811 v1(35.614,65.347) ; v1(44.041,36.33) 44.041,35.605 41.858,33.423 41.858,23.298 44.609,20.548 47.576,20.548 49.596,18.527 49.596,16.01 49.776,15.83 v1(49.776,15.41) ; v1(76.296,7.888) 75.816,7.409 75.816,6.64 77.154,5.302 J14.16@77.154,3.76
NetJ2_30: J2.30 J14.15 | length 99.6
  TOP w0.15: J2.30@35.9,58.96 35.9,58.51 35.827,58.437 35.827,57.819 35.447,57.439 35.447,44.631 41.8,38.279 45.265,38.279 v1(45.552,37.992) ; v1(52.4,15.3) 52.4,15.191 53.239,14.352 53.738,14.352 54.39,13.7 70.822,13.7 74.054,10.468 76.705,10.468 78.236,8.937 v1(81.391,8.937)
  SIG w0.15: v1(45.552,37.992) 46.052,37.492 46.052,36.05 42.966,32.964 42.966,23.757 45.068,21.656 48.035,21.656 52.4,17.291 v1(52.4,15.3) ; J14.15@77.154,1.22 78.409,2.475 78.409,5.982 79.051,6.624 79.051,8.624 79.448,9.021 81.307,9.021 v1(81.391,8.937)
NetJ2_31: J2.31 J14.24 | length 109.4
  TOP w0.15: v1(32.46,51.051) 33.555,49.956 33.555,45.348 41.68,37.223 v1(43.858,37.223) ; J2.31@36.3,62.04 36.3,63.257 36.21,63.347 36.21,63.763 36.3,63.853 36.3,64.431 v1(36.385,64.517) ; v1(50.5,15.5) 50.581,15.419 50.581,15.1 52.16,13.521 53.394,13.521 54.046,12.869 70.445,12.869 73.879,9.434 75.753,9.434 v1(76.456,8.731)
  SIG w0.15: v1(32.46,51.051) 32.46,51.686 34.006,53.232 34.006,63.135 35.387,64.517 v1(36.385,64.517) ; v1(43.858,37.223) 44.618,36.463 44.618,35.791 42.135,33.308 42.135,23.413 44.724,20.825 47.691,20.825 50.165,18.351 50.165,15.835 v1(50.5,15.5) ; v1(76.456,8.731) 77.267,9.543 82.456,9.543 87.289,4.71 87.289,3.785 J14.24@87.314,3.76
NetJ2_32: J2.32 J14.23 | length 99.4
  TOP w0.15: J2.32@36.3,58.96 36.3,58.51 36.227,58.437 36.227,57.827 35.724,57.324 35.724,44.746 41.904,38.566 45.69,38.566 v1(46.493,37.762) ; v1(53.201,15.281) 54.505,13.977 71.021,13.977 74.237,10.761 76.894,10.761 78.112,9.543 81.747,9.543 v1(83.016,8.273)
  SIG w0.15: v1(46.493,37.762) 46.46,37.728 46.46,36.065 43.243,32.849 43.243,23.872 45.183,21.933 48.15,21.933 53.201,16.882 v1(53.201,15.281) ; v1(83.016,8.273) 83.024,8.273 85.826,5.471 85.826,3.76 87.314,2.272 J14.23@87.314,1.22
NetJ2_35: J2.35 J15.10 | length 54.4
  TOP w0.15: J2.35@37.1,62.04 37.1,63.198 ; v1(66.3,77.7) 67.214,77.7 68.25,78.736 68.25,83.936 J15.10@69.534,85.22
  TOP w0.2: v1(36.488,65.236) 36.549,65.236 37.239,64.546 37.239,63.337 37.1,63.198
  SIG w0.15: v1(60.96,74.239) 60.96,75.011 64.09,78.141 65.859,78.141 v1(66.3,77.7)
  BOTTOM w0.15: v1(36.488,65.236) 36.549,65.236 37.239,64.546 37.239,61.313 37.586,60.966 44.912,60.966 46.298,62.352 48.822,62.352 50.182,63.711 50.182,63.936 60.484,74.239 v1(60.96,74.239)
NetJ2_36: J2.36 J15.18 | length 60.6
  TOP w0.15: J2.36@37.1,58.96 37.1,57.518 37.178,57.44 37.178,56.273 v1(37.722,55.729)
  SIG w0.15: v1(62.954,75.025) 62.957,75.029 63.843,75.029 64.071,75.257 66.806,75.257 68.45,76.901 74.515,76.901 78.463,80.848 78.463,83.989 J15.18@79.694,85.22
  BOTTOM w0.15: v1(37.722,55.729) 42.664,55.729 48.059,61.124 48.582,61.124 49.217,61.759 50.817,61.759 52.002,62.944 52.002,64.076 60.228,72.302 60.878,72.302 62.954,74.378 v1(62.954,75.025)
NetJ2_37: J2.37 J15.12 | length 49.2
  TOP w0.15: J2.37@37.5,62.04 37.5,63.135
  TOP w0.2: v1(37.18,65.458) 37.19,65.449 37.19,65.058 37.566,64.682 37.566,63.201 37.5,63.135
  SIG w0.15: v1(70.45,79.701) 70.45,79.747 70.822,80.119 70.822,83.968 J15.12@72.074,85.22
  BOTTOM w0.15: v1(37.18,65.458) 37.219,65.497 37.219,65.858 39.347,67.986 45.246,67.986 45.26,68 46.97,68 47.163,68.194 50.522,68.194 59.391,77.063 59.46,77.063 61.873,79.476 70.225,79.476 v1(70.45,79.701)
NetJ2_38: J2.38 J15.20 | length 62.5
  TOP w0.15: J2.38@37.5,58.96 37.5,58.393 37.455,58.348 37.455,56.695 37.855,56.295 37.866,56.295 38.516,55.645 v1(38.516,55.227)
  SIG w0.15: v1(63.733,74.527) 64.186,74.98 66.92,74.98 68.497,76.557 74.991,76.557 78.988,80.554 78.988,81.282 v1(78.998,81.292)
  BOTTOM w0.15: v1(38.516,55.227) 38.574,55.285 38.916,55.285 39.008,55.376 40.733,55.376 40.809,55.452 42.779,55.452 48.173,60.847 48.697,60.847 49.331,61.482 50.932,61.482 52.279,62.829 52.279,63.961 60.343,72.025 61,72.025 62.556,73.581 62.787,73.581 v1(63.733,74.527) ; v1(78.998,81.292) 80.141,81.292 80.95,82.101 80.95,83.936 J15.20@82.234,85.22
NetJ2_39: J2.39 J15.14 | length 56.9
  TOP w0.15: J2.39@37.9,62.04 37.9,63.782 ; v1(70.9,77.8) 71.6,77.8 73.35,79.55 73.35,83.956 J15.14@74.614,85.22
  TOP w0.2: 37.904,63.786 v1(37.904,65.389)
  SIG w0.15: v1(64.087,75.973) 64.815,76.701 67.05,76.701 68.196,77.847 70.853,77.847 v1(70.9,77.8)
  BOTTOM w0.15: v1(37.904,65.389) 37.606,65.092 37.606,61.829 38.193,61.243 44.797,61.243 46.183,62.629 48.64,62.629 49.905,63.894 49.905,64.051 60.369,74.516 60.527,74.516 61.931,75.92 64.034,75.92 v1(64.087,75.973)
NetJ2_40: J2.40 J15.22 | length 66.5
  TOP w0.15: J2.40@37.9,58.96 37.9,58.402 37.732,58.233 37.732,56.823 39.172,55.383 39.172,54.918 v1(39.216,54.874)
  SIG w0.15: v1(80.2,76) 80.198,76.002 80.198,77.449 83.45,80.701 83.45,83.896 J15.22@84.774,85.22
  BOTTOM w0.15: v1(39.216,54.874) 39.645,54.874 39.87,55.099 40.847,55.099 40.924,55.175 42.893,55.175 48.288,60.57 48.811,60.57 49.446,61.205 51.046,61.205 52.556,62.715 52.556,63.847 60.458,71.748 61.115,71.748 62.67,73.304 63.271,73.304 65.431,75.464 66.594,75.464 67.348,76.218 79.03,76.218 79.248,76 v1(80.2,76)
NetJ2_41: J2.41 J15.16 | length 59.4
  TOP w0.15: J2.41@38.3,62.04 38.3,63.098 ; v1(73.4,77.7) 75.844,80.144 75.844,84.652 76.204,85.013 76.947,85.013 J15.16@77.154,85.22
  TOP w0.2: 38.289,63.11 38.289,64.469 38.649,64.829 v1(38.649,65.329)
  SIG w0.15: v1(66.198,75.992) 66.248,76.042 67.191,76.042 68.447,77.298 72.998,77.298 v1(73.4,77.7)
  BOTTOM w0.15: v1(38.649,65.329) 37.933,64.613 37.933,62.007 38.421,61.52 44.682,61.52 46.068,62.906 48.525,62.906 49.628,64.008 49.628,64.166 60.255,74.793 60.412,74.793 62.094,76.475 64.295,76.475 64.777,75.992 v1(66.198,75.992)
NetJ2_42: J2.42 J15.24 | length 72.9
  TOP w0.15: J2.42@38.3,58.96 38.3,58.329 38.009,58.038 38.009,56.984 39.718,55.275 39.718,54.911 v1(40.054,54.574)
  SIG w0.15: v1(87.1,76) 87.05,76.05 87.05,79.612 88.383,80.945 88.383,81.189 88.596,81.401 88.596,83.85 87.314,85.132 J15.24@87.314,85.22
  BOTTOM w0.15: v1(40.054,54.574) 42.064,54.574 42.388,54.898 43.008,54.898 48.403,60.293 48.926,60.293 49.561,60.928 51.161,60.928 52.833,62.6 52.833,63.732 60.572,71.471 61.262,71.471 62.818,73.027 63.385,73.027 65.546,75.187 66.709,75.187 67.371,75.85 79.006,75.85 79.447,75.409 80.936,75.409 81.766,76.239 86.787,76.239 87.026,76 v1(87.1,76)
NetJ2_45: J2.45 J15.34 | length 80.9
  TOP w0.15: J2.45@39.1,62.04 39.1,62.526 39.325,62.751 39.325,64.121 v1(39.37,64.165)
  SIG w0.15: v1(98.164,75.618) 98.164,77.549 98.036,77.678 98.036,79.487 98.761,80.212 98.761,83.967 J15.34@100.014,85.22
  BOTTOM w0.15: v1(39.37,64.165) 39.352,64.147 39.352,62.052 39.607,61.797 44.567,61.797 45.954,63.183 48.41,63.183 49.351,64.123 49.351,64.281 60.14,75.07 60.297,75.07 61.979,76.752 64.41,76.752 64.616,76.545 85.667,76.545 86.115,76.992 89.559,76.992 90.39,76.161 97.621,76.161 v1(98.164,75.618)
NetJ2_47: J2.47 J15.36 | length 83.1
  TOP w0.15: J2.47@39.5,62.04 39.5,62.534 39.602,62.636 39.602,63.688 39.872,63.957 39.872,65.227 v1(39.875,65.23)
  SIG w0.15: v1(100.524,76.921) 100.566,76.963 100.566,78.366 101.28,79.08 101.28,83.946 J15.36@102.554,85.22
  BOTTOM w0.15: v1(39.875,65.23) 39.875,62.515 40.317,62.074 44.412,62.074 45.798,63.46 48.296,63.46 49.074,64.238 49.074,64.395 60.025,75.347 60.183,75.347 61.865,77.029 64.524,77.029 64.731,76.822 85.553,76.822 86,77.269 89.673,77.269 90.505,76.438 91.495,76.438 91.979,76.921 v1(100.524,76.921)
NetJ2_49: J2.49 J15.38 | length 85.6
  TOP w0.15: v1(39.675,66.258) 39.741,66.192 40.052,66.192 40.509,65.735 40.509,65.154 40.149,64.794 40.149,63.842 39.879,63.573 39.879,62.527 39.9,62.507 J2.49@39.9,62.04
  SIG w0.15: v1(101.5,78.1) 103.85,80.45 103.85,83.976 J15.38@105.094,85.22
  BOTTOM w0.15: v1(39.675,66.258) 40.377,65.556 40.377,62.623 40.649,62.351 44.297,62.351 45.684,63.737 48.181,63.737 48.797,64.353 48.797,64.51 59.965,75.678 60.122,75.678 61.75,77.306 64.639,77.306 64.846,77.099 85.438,77.099 85.885,77.546 93.253,77.546 93.256,77.543 94.143,77.543 94.717,78.117 101.483,78.117 v1(101.5,78.1)
NetJ2_51: J2.51 J15.40 | length 83
  TOP w0.15: v1(40.129,66.853) 40.786,66.197 40.786,65.039 40.426,64.679 40.426,63.728 40.3,63.602 J2.51@40.3,62.04
  BOTTOM w0.15: v1(40.129,66.853) 40.251,66.853 40.404,67.006 40.419,67.006 41.099,67.686 45.338,67.686 45.375,67.723 46.701,67.723 46.738,67.686 50.406,67.686 59.506,76.786 59.663,76.786 62.076,79.199 106.048,79.199 106.35,79.501 106.35,83.936 J15.40@107.634,85.22
NetJ2_53: J2.53 J15.42 | length 84.5
  TOP w0.15: J2.53@40.709,62.049 40.709,64.571 41.063,64.925 41.063,66.677 v1(40.997,66.742)
  BOTTOM w0.15: v1(40.997,66.742) 41.071,66.816 41.071,67.111 41.37,67.409 45.453,67.409 45.49,67.446 46.586,67.446 46.623,67.409 50.521,67.409 59.621,76.509 59.778,76.509 62.191,78.922 108.371,78.922 108.95,79.501 108.95,83.996 J15.42@110.174,85.22
NetJ2_55: J2.55 J15.44 | length 86.3
  TOP w0.15: J2.55@41.1,62.04 41.1,64.57 41.34,64.81 41.34,66.375 41.763,66.798 v1(41.763,66.907)
  BOTTOM w0.15: v1(41.763,66.907) 42.495,66.907 42.72,67.132 45.567,67.132 45.605,67.169 46.471,67.169 46.508,67.132 50.636,67.132 59.736,76.232 59.893,76.232 62.305,78.645 110.49,78.645 111.45,79.604 111.45,83.956 J15.44@112.714,85.22
NetJ2_71: J2.71 J15.7 | length 34.3
  TOP w0.15: J2.71@44.3,62.04 44.3,62.552 44.392,62.645 44.392,63.614 45.883,65.105 45.883,66.091 46.149,66.357 v1(46.149,66.39)
  SIG w0.15: v1(46.149,66.39) 46.149,66.455 46.549,66.855 50.342,66.855 63.239,79.753 66.64,79.753 66.994,80.106 J15.7@66.994,82.68
NetJ2_73: J2.73 J15.9 | length 36.1
  TOP w0.15: J2.73@44.7,62.04 44.7,63.53 46.33,65.16 46.33,65.843 46.794,66.307 v1(46.871,66.307)
  SIG w0.15: v1(46.871,66.307) 46.993,66.307 47.104,66.418 50.297,66.418 63.354,79.476 68.87,79.476 69.534,80.14 J15.9@69.534,82.68
NetJ2_74: J2.74 J15.17 | length 50.2
  TOP w0.15: J2.74@44.7,58.96 44.7,57.987 45.294,57.392 46.996,57.392 47.025,57.421 47.337,57.421 v1(47.62,57.138)
  SIG w0.15: v1(61.695,71.194) 62.884,72.382 65.963,72.382 68.869,75.289 74.543,75.289 76.2,76.946 76.927,77.673 76.927,78.101 79.694,80.868 J15.17@79.694,82.68
  BOTTOM w0.15: v1(47.62,57.138) 47.702,57.22 47.702,57.538 47.821,57.657 47.821,58.811 48.749,59.739 49.156,59.739 49.79,60.374 50.733,60.374 51.667,60.374 57.089,65.797 57.089,67.596 60.687,71.194 v1(61.695,71.194)
NetJ2_75: J2.75 J15.11 | length 37.9
  TOP w0.15: J2.75@45.1,62.04 45.1,63.256 46.906,65.062 46.906,65.286 v1(46.992,65.372)
  SIG w0.15: v1(46.992,65.372) 46.993,65.374 49.644,65.374 63.469,79.199 71.133,79.199 72.074,80.14 J15.11@72.074,82.68
NetJ2_76: J2.76 J15.19 | length 51.8
  TOP w0.15: J2.76@45.1,58.96 45.1,57.979 45.34,57.739 47.56,57.739 47.621,57.8 47.884,57.8 48.294,57.39 v1(48.323,57.39)
  SIG w0.15: v1(57.6,67) 61.292,70.692 62.101,70.692 62.165,70.757 64.906,70.757 69.161,75.012 76.718,75.012 82.234,80.527 J15.19@82.234,82.68
  BOTTOM w0.15: v1(48.323,57.39) 48.323,57.867 48.098,58.092 48.098,58.563 48.997,59.462 49.27,59.462 49.905,60.097 51.505,60.097 51.781,60.097 57.6,65.916 v1(57.6,67)
NetJ2_77: J2.77 J15.13 | length 39.8
  TOP w0.15: J2.77@45.5,62.04 45.5,63.076 47.209,64.786 47.433,64.786 v1(47.519,64.872)
  SIG w0.15: v1(47.519,64.872) 47.558,64.833 49.495,64.833 63.558,78.896 73.37,78.896 74.614,80.14 J15.13@74.614,82.68
NetJ2_78: J2.78 J15.21 | length 54.5
  TOP w0.15: J2.78@45.5,58.96 45.5,58.454 45.938,58.016 47.445,58.016 47.729,58.3 v1(48.6,58.3)
  SIG w0.15: v1(58.2,66.4) 62.28,70.48 65.021,70.48 69.276,74.735 83.847,74.735 84.774,75.662 84.774,80.269 J15.21@84.774,82.68
  BOTTOM w0.15: v1(48.6,58.3) 48.622,58.3 49.035,58.713 49.035,58.835 50.02,59.82 51.896,59.82 57.877,65.801 57.877,66.077 v1(58.2,66.4)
